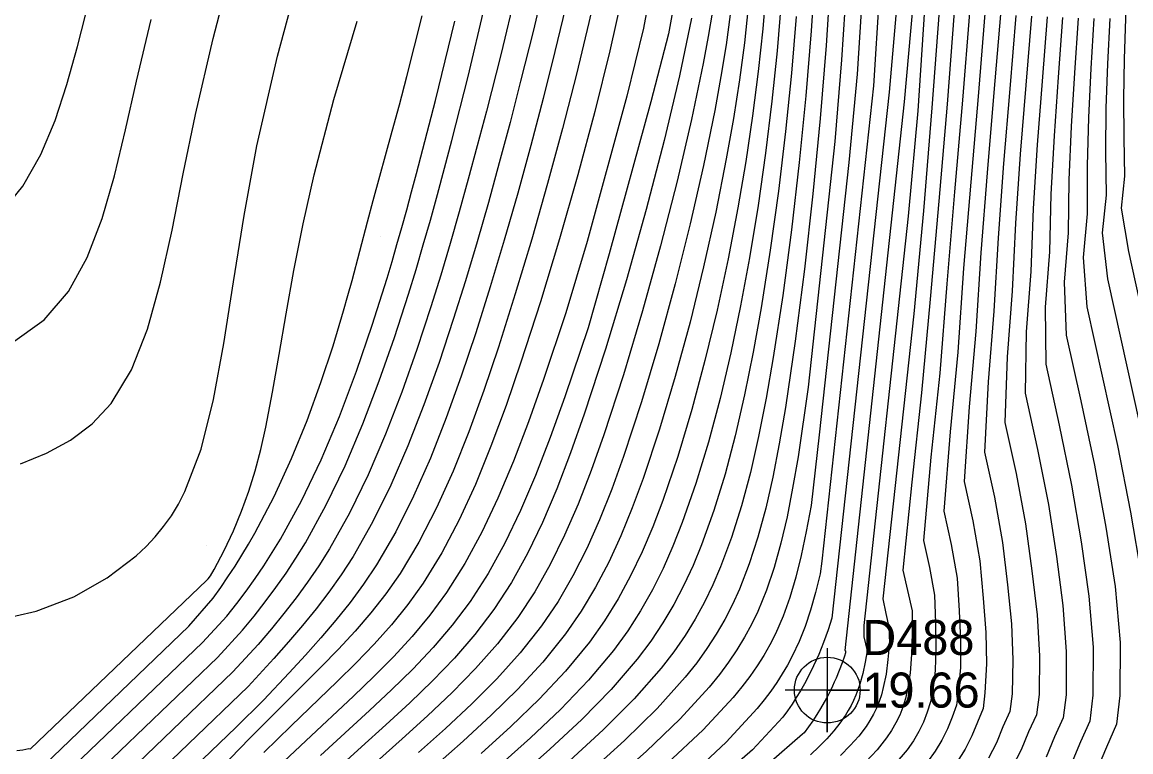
# Model space of a CAD drawing. Extents: x 2356077 to 2359823, y 225951 to 227822.
# Drawn here: x 2356768.9 to 2356848, y 226939 to 226991.1 of the extents above; entities that cross this region are included whole.
import ezdxf

# ---------------------------------------------------------------- set-up
doc = ezdxf.new("R2010")
doc.units = 0
for name, color, linetype in [('DTM Contours Major', 7, 'Continuous'), ('DTM Contours Minor', 7, 'Continuous'), ('Exist DTM Regular Point CELL', 7, 'Continuous'), ('Exist DTM Regular Point Cogo Elevation', 7, 'Continuous'), ('Exist DTM Regular Point Cogo Number', 7, 'Continuous'), ('PH Exist DTM Point', 7, 'Continuous')]:
    doc.layers.add(name, color=color, linetype=linetype)

msp = doc.modelspace()

# ---------------------------------------------------------------- linework, layer by layer
at = {"layer": 'DTM Contours Major'}
for points in [[(2356809.909, 226993.635), (2356809.32, 226991.039), (2356808.425, 226987.333), (2356807.438, 226983.481), (2356806.373, 226979.545), (2356805.246, 226975.589), (2356804.071, 226971.678), (2356802.862, 226967.875), (2356801.819, 226964.784), (2356800.747, 226961.832), (2356799.629, 226959.037), (2356798.452, 226956.414), (2356797.198, 226953.98), (2356795.853, 226951.751), (2356794.838, 226950.302), (2356793.769, 226948.938), (2356792.646, 226947.631), (2356791.467, 226946.356), (2356790.233, 226945.087), (2356788.944, 226943.796), (2356787.073, 226941.938), (2356785.109, 226939.968), (2356783.064, 226937.861)], [(2356830.007, 226992.945), (2356829.607, 226986.516), (2356825.924, 226952.62), (2356825.802, 226951.72), (2356825.476, 226950.376), (2356825.123, 226949.133), (2356824.736, 226947.975), (2356824.306, 226946.888), (2356823.823, 226945.856), (2356823.482, 226945.215), (2356823.113, 226944.587), (2356822.715, 226943.968), (2356822.286, 226943.354), (2356821.823, 226942.741), (2356821.326, 226942.124), (2356819.099, 226939.709), (2356816.463, 226937.248)], [(2356818.127, 226991.834), (2356817.829, 226990.035), (2356817.471, 226988.108), (2356816.631, 226984.102), (2356815.603, 226979.718), (2356814.427, 226975.115), (2356813.139, 226970.458), (2356811.778, 226965.907), (2356810.381, 226961.623), (2356809.476, 226959.077), (2356808.552, 226956.696), (2356807.587, 226954.47), (2356806.562, 226952.386), (2356805.454, 226950.433), (2356804.262, 226948.596), (2356802.802, 226946.729), (2356801.235, 226944.957), (2356799.566, 226943.257), (2356797.817, 226941.602), (2356796.008, 226939.965), (2356794.163, 226938.318)], [(2356768.047, 226968.083), (2356770.473, 226969.83), (2356772.197, 226971.856), (2356773.546, 226974.28), (2356774.614, 226977.045), (2356775.492, 226980.096), (2356776.274, 226983.378), (2356777.05, 226986.834), (2356778.1, 226991.252)], [(2356770.848, 226936.354), (2356781.758, 226946.817), (2356783.504, 226948.699), (2356784.2, 226949.595), (2356784.87, 226950.49), (2356785.515, 226951.389), (2356786.137, 226952.299), (2356786.739, 226953.228), (2356787.323, 226954.181), (2356788.833, 226956.921), (2356790.233, 226959.856), (2356791.534, 226962.947), (2356792.744, 226966.16), (2356793.87, 226969.457), (2356794.921, 226972.802), (2356795.278, 226973.996), (2356795.63, 226975.2), (2356795.978, 226976.421), (2356796.326, 226977.667), (2356796.676, 226978.947), (2356797.031, 226980.268), (2356798.376, 226985.47), (2356799.747, 226991.115)], [(2356824.099, 226991.457), (2356823.764, 226987.423), (2356823.341, 226983.244), (2356822.836, 226979.006), (2356822.257, 226974.795), (2356821.611, 226970.695), (2356821.042, 226967.515), (2356820.426, 226964.47), (2356819.757, 226961.569), (2356819.026, 226958.818), (2356818.228, 226956.225), (2356817.354, 226953.796), (2356816.747, 226952.322), (2356816.093, 226950.908), (2356815.381, 226949.543), (2356814.598, 226948.217), (2356813.732, 226946.917), (2356812.771, 226945.633), (2356810.912, 226943.473), (2356808.812, 226941.33), (2356806.539, 226939.206), (2356804.161, 226937.103)], [(2356835.373, 226991.796), (2356834.857, 226985.213), (2356834.264, 226978.279), (2356833.659, 226971.29), (2356833.044, 226964.612), (2356832.353, 226958.246), (2356831.718, 226951.989), (2356832.361, 226949.074), (2356832.371, 226947.454), (2356832.327, 226945.977), (2356832.229, 226944.652), (2356832.05, 226943.46), (2356831.9, 226942.824), (2356831.712, 226942.221), (2356831.485, 226941.646), (2356831.217, 226941.092), (2356830.906, 226940.555), (2356830.55, 226940.029), (2356829.864, 226939.174), (2356829.058, 226938.318)], [(2356840.879, 226991.473), (2356840.084, 226981.638), (2356839.741, 226976.721), (2356839.512, 226971.868), (2356839.143, 226967.194), (2356838.98, 226962.506), (2356839.782, 226958.875), (2356840.449, 226955.29), (2356840.913, 226951.936), (2356841.279, 226948.792), (2356841.445, 226945.877), (2356841.42, 226943.121), (2356841.233, 226941.667), (2356840.67, 226940.446), (2356840.15, 226939.164), (2356839.498, 226937.933)], [(2356846.463, 226991.315), (2356846.306, 226988.069), (2356846.19, 226984.918), (2356846.149, 226981.814), (2356846.211, 226978.707), (2356845.921, 226976.037), (2356846.301, 226972.756), (2356848.604, 226962.327)]]:
    msp.add_lwpolyline(points, dxfattribs=at)
at = {"layer": 'DTM Contours Minor'}
for points in [[(2356848.021, 227001.185), (2356847.797, 226996.149), (2356847.597, 226991.324), (2356847.499, 226988.406), (2356847.447, 226985.582), (2356847.465, 226982.801), (2356847.523, 226980.071), (2356847.277, 226977.801), (2356847.79, 226974.694), (2356851.417, 226958.266)], [(2356766.972, 226948.397), (2356769.899, 226949.052), (2356772.578, 226950.084), (2356774.97, 226951.424), (2356777.036, 226953.002), (2356777.739, 226953.662), (2356778.39, 226954.354), (2356778.99, 226955.084), (2356779.543, 226955.86), (2356780.05, 226956.689), (2356780.513, 226957.577), (2356781.662, 226960.597), (2356782.551, 226964.14), (2356783.286, 226968.141), (2356783.975, 226972.534), (2356784.724, 226977.255), (2356785.643, 226982.239), (2356787.108, 226988.625), (2356788.857, 226995.076)], [(2356768.791, 226959.569), (2356770.636, 226960.323), (2356772.353, 226961.255), (2356773.906, 226962.419), (2356775.261, 226963.869), (2356776.708, 226966.26), (2356777.85, 226969.163), (2356778.78, 226972.506), (2356779.595, 226976.218), (2356780.389, 226980.229), (2356781.257, 226984.466), (2356782.525, 226989.888), (2356783.962, 226995.383)], [(2356814.063, 226995.245), (2356813.202, 226990.635), (2356812.02, 226985.774), (2356809.185, 226975.404), (2356807.672, 226970.338), (2356806.082, 226965.579), (2356805.01, 226962.562), (2356803.935, 226959.744), (2356802.835, 226957.122), (2356801.69, 226954.69), (2356800.475, 226952.444), (2356799.17, 226950.38), (2356797.981, 226948.767), (2356796.717, 226947.251), (2356795.383, 226945.804), (2356793.982, 226944.395), (2356792.522, 226942.996), (2356789.131, 226939.821), (2356787.193, 226937.976)], [(2356815.826, 226994.835), (2356814.989, 226990.209), (2356813.731, 226985.368), (2356810.77, 226974.533), (2356809.259, 226969.249), (2356807.6, 226964.343), (2356806.55, 226961.437), (2356805.501, 226958.733), (2356804.43, 226956.223), (2356803.312, 226953.896), (2356802.125, 226951.742), (2356800.846, 226949.752), (2356799.571, 226948.054), (2356798.208, 226946.456), (2356796.766, 226944.93), (2356795.253, 226943.445), (2356793.68, 226941.972), (2356790.185, 226938.759)], [(2356825.446, 226994.757), (2356825.167, 226990.424), (2356824.785, 226985.807), (2356824.313, 226981.038), (2356823.761, 226976.247), (2356823.141, 226971.567), (2356822.464, 226967.131), (2356821.961, 226964.233), (2356821.424, 226961.51), (2356820.842, 226958.955), (2356820.204, 226956.559), (2356819.499, 226954.314), (2356818.714, 226952.212), (2356818.161, 226950.93), (2356817.561, 226949.694), (2356816.903, 226948.494), (2356816.178, 226947.318), (2356815.374, 226946.157), (2356814.482, 226945), (2356812.546, 226942.803), (2356810.339, 226940.596), (2356807.942, 226938.391)], [(2356826.558, 226994.268), (2356826.241, 226989.392), (2356825.814, 226984.173), (2356825.279, 226978.809), (2356824.696, 226973.449), (2356824.04, 226968.315), (2356823.336, 226963.581), (2356822.896, 226960.998), (2356822.431, 226958.609), (2356821.928, 226956.394), (2356821.373, 226954.337), (2356820.752, 226952.42), (2356820.051, 226950.623), (2356819.552, 226949.523), (2356819.005, 226948.457), (2356818.404, 226947.415), (2356817.74, 226946.387), (2356817.006, 226945.365), (2356816.193, 226944.34), (2356814.183, 226942.112), (2356811.869, 226939.845), (2356809.346, 226937.562)], [(2356806.226, 226994.187), (2356805.358, 226990.488), (2356804.452, 226986.847), (2356803.695, 226983.909), (2356802.93, 226981.025), (2356802.15, 226978.187), (2356801.348, 226975.385), (2356800.516, 226972.608), (2356799.65, 226969.847), (2356798.634, 226966.787), (2356797.559, 226963.773), (2356796.415, 226960.844), (2356795.197, 226958.038), (2356793.896, 226955.396), (2356792.504, 226952.955), (2356791.66, 226951.653), (2356790.78, 226950.411), (2356789.862, 226949.212), (2356788.904, 226948.034), (2356787.902, 226946.861), (2356786.854, 226945.672), (2356785.025, 226943.695), (2356776.5, 226935.519)], [(2356821.96, 226993.528), (2356821.717, 226990.584), (2356821.393, 226987.524), (2356820.988, 226984.364), (2356820.504, 226981.118), (2356819.94, 226977.803), (2356819.243, 226974.17), (2356818.461, 226970.527), (2356817.598, 226966.93), (2356816.66, 226963.432), (2356815.655, 226960.088), (2356814.587, 226956.952), (2356813.867, 226955.065), (2356813.107, 226953.276), (2356812.292, 226951.571), (2356811.406, 226949.939), (2356810.433, 226948.368), (2356809.356, 226946.847), (2356807.659, 226944.782), (2356805.775, 226942.778), (2356803.75, 226940.822), (2356801.629, 226938.901)], [(2356827.681, 226993.798), (2356827.33, 226988.365), (2356826.849, 226982.554), (2356824.945, 226965.034), (2356824.233, 226960.062), (2356823.849, 226957.825), (2356823.447, 226955.777), (2356823.01, 226953.896), (2356822.526, 226952.159), (2356821.98, 226950.545), (2356821.357, 226949.031), (2356820.91, 226948.099), (2356820.419, 226947.192), (2356819.878, 226946.301), (2356819.282, 226945.418), (2356818.625, 226944.535), (2356817.901, 226943.644), (2356815.821, 226941.386), (2356813.402, 226939.062), (2356810.751, 226936.703)], [(2356767.305, 226977.352), (2356768.945, 226979.367), (2356770.232, 226981.605), (2356771.253, 226984.033), (2356772.095, 226986.618), (2356772.844, 226989.327), (2356773.737, 226992.787)], [(2356804.094, 226993.113), (2356803.057, 226988.816), (2356802.012, 226984.714), (2356801.361, 226982.234), (2356800.719, 226979.848), (2356800.076, 226977.531), (2356799.423, 226975.259), (2356798.75, 226973.01), (2356798.047, 226970.758), (2356797.045, 226967.712), (2356795.968, 226964.668), (2356794.811, 226961.675), (2356793.57, 226958.781), (2356792.239, 226956.036), (2356790.814, 226953.489), (2356790.051, 226952.28), (2356789.259, 226951.121), (2356788.435, 226949.996), (2356787.575, 226948.891), (2356786.678, 226947.791), (2356785.739, 226946.682), (2356783.923, 226944.723), (2356775.317, 226936.47)], [(2356811.721, 226993.075), (2356810.812, 226989.014), (2356809.737, 226984.671), (2356808.53, 226980.163), (2356807.227, 226975.605), (2356805.861, 226971.113), (2356804.467, 226966.802), (2356803.409, 226963.724), (2356802.335, 226960.821), (2356801.226, 226958.098), (2356800.064, 226955.561), (2356798.829, 226953.214), (2356797.502, 226951.063), (2356796.399, 226949.528), (2356795.231, 226948.086), (2356794.001, 226946.708), (2356792.712, 226945.366), (2356791.364, 226944.032), (2356788.09, 226940.878), (2356786.144, 226938.978)], [(2356831.307, 226992.649), (2356830.721, 226986.06), (2356826.646, 226948.559), (2356826.374, 226947.721), (2356826.052, 226946.83), (2356825.709, 226945.977), (2356825.343, 226945.157), (2356824.951, 226944.366), (2356824.684, 226943.87), (2356824.404, 226943.383), (2356824.111, 226942.903), (2356823.804, 226942.428), (2356823.484, 226941.959), (2356823.149, 226941.492), (2356820.979, 226939.176), (2356808.524, 226928.333)], [(2356828.823, 226993.35), (2356828.453, 226987.355), (2356827.85, 226981.057), (2356825.738, 226961.621), (2356825.159, 226956.594), (2356824.822, 226954.731), (2356824.467, 226953.03), (2356824.081, 226951.472), (2356823.654, 226950.034), (2356823.171, 226948.696), (2356822.62, 226947.437), (2356822.224, 226946.659), (2356821.791, 226945.898), (2356821.317, 226945.148), (2356820.798, 226944.403), (2356820.23, 226943.657), (2356819.609, 226942.904), (2356817.46, 226940.6), (2356814.935, 226938.214)], [(2356774.148, 226937.433), (2356782.828, 226945.758), (2356784.619, 226947.695), (2356785.444, 226948.711), (2356786.233, 226949.723), (2356786.99, 226950.74), (2356787.719, 226951.773), (2356788.421, 226952.832), (2356789.099, 226953.929), (2356790.564, 226956.58), (2356791.929, 226959.423), (2356793.196, 226962.405), (2356794.369, 226965.474), (2356795.454, 226968.578), (2356796.452, 226971.665), (2356796.99, 226973.418), (2356797.509, 226975.17), (2356798.015, 226976.943), (2356798.518, 226978.76), (2356799.023, 226980.642), (2356799.54, 226982.612), (2356800.701, 226987.188), (2356801.883, 226992.109)], [(2356807.648, 226992.098), (2356806.891, 226988.96), (2356806.051, 226985.618), (2356805.169, 226982.248), (2356804.247, 226978.87), (2356803.286, 226975.506), (2356802.287, 226972.174), (2356801.252, 226968.895), (2356800.221, 226965.815), (2356799.146, 226962.829), (2356798.016, 226959.965), (2356796.819, 226957.249), (2356795.544, 226954.708), (2356794.18, 226952.37), (2356793.254, 226950.986), (2356792.285, 226949.672), (2356791.271, 226948.407), (2356790.21, 226947.167), (2356789.102, 226945.929), (2356787.943, 226944.67), (2356786.108, 226942.701), (2356784.138, 226940.76), (2356777.676, 226934.562)], [(2356820.68, 226992.129), (2356820.404, 226989.589), (2356820.053, 226986.943), (2356819.624, 226984.186), (2356819.116, 226981.31), (2356818.362, 226977.513), (2356817.495, 226973.601), (2356816.529, 226969.66), (2356815.479, 226965.776), (2356814.361, 226962.035), (2356813.189, 226958.523), (2356812.409, 226956.419), (2356811.596, 226954.434), (2356810.731, 226952.555), (2356809.797, 226950.77), (2356808.776, 226949.068), (2356807.651, 226947.437), (2356806.037, 226945.43), (2356804.26, 226943.501), (2356802.355, 226941.63), (2356800.361, 226939.799), (2356798.314, 226937.988)], [(2356823.031, 226992.491), (2356822.743, 226989.015), (2356822.37, 226985.408), (2356821.914, 226981.715), (2356821.38, 226977.983), (2356820.77, 226974.258), (2356820.136, 226970.831), (2356819.438, 226967.479), (2356818.674, 226964.23), (2356817.844, 226961.111), (2356816.945, 226958.15), (2356815.976, 226955.376), (2356815.314, 226953.7), (2356814.607, 226952.101), (2356813.843, 226950.568), (2356813.007, 226949.089), (2356812.085, 226947.652), (2356811.063, 226946.247), (2356809.284, 226944.131), (2356807.293, 226942.056), (2356805.144, 226940.015), (2356802.896, 226938.003)], [(2356832.41, 226992.266), (2356831.809, 226985.365), (2356827.559, 226946.255), (2356827.611, 226946.217), (2356827.614, 226946.096), (2356827.548, 226945.853), (2356827.377, 226945.37), (2356827.169, 226944.821), (2356826.95, 226944.291), (2356826.819, 226943.992), (2356826.684, 226943.698), (2356826.545, 226943.409), (2356826.402, 226943.124), (2356826.254, 226942.844), (2356826.102, 226942.568), (2356825.842, 226942.12), (2356825.568, 226941.68), (2356825.281, 226941.247), (2356824.979, 226940.817), (2356824.663, 226940.391), (2356824.551, 226940.282), (2356812.545, 226929.831)], [(2356833.245, 226991.968), (2356832.767, 226984.741), (2356832.086, 226977.208), (2356828.917, 226948.041), (2356828.933, 226947.237), (2356829.154, 226946.237), (2356829.029, 226945.421), (2356828.849, 226944.606), (2356828.641, 226943.859), (2356828.504, 226943.453), (2356828.355, 226943.064), (2356828.192, 226942.69), (2356828.014, 226942.328), (2356827.819, 226941.976), (2356827.607, 226941.631), (2356827.219, 226941.073), (2356826.778, 226940.52), (2356826.284, 226939.963), (2356825.735, 226939.396), (2356825.129, 226938.81)], [(2356834.291, 226991.868), (2356833.777, 226984.952), (2356833.169, 226977.602), (2356832.494, 226970.258), (2356830.287, 226949.94), (2356830.486, 226948.884), (2356830.702, 226947.905), (2356830.75, 226946.796), (2356830.645, 226945.619), (2356830.506, 226944.561), (2356830.315, 226943.608), (2356830.176, 226943.097), (2356830.012, 226942.611), (2356829.823, 226942.148), (2356829.607, 226941.702), (2356829.362, 226941.269), (2356829.086, 226940.844), (2356828.563, 226940.155), (2356827.953, 226939.467), (2356827.255, 226938.767)], [(2356768.516, 226939.113), (2356768.953, 226939.175), (2356769.388, 226939.26), (2356769.503, 226939.233), (2356782.037, 226951.254), (2356782.169, 226951.366), (2356782.34, 226951.581), (2356782.597, 226952.033), (2356782.843, 226952.482), (2356783.08, 226952.928), (2356783.307, 226953.372), (2356783.971, 226954.775), (2356784.552, 226956.178), (2356785.063, 226957.601), (2356785.514, 226959.063), (2356785.916, 226960.583), (2356786.28, 226962.178), (2356786.767, 226964.666), (2356787.237, 226967.357), (2356787.729, 226970.252), (2356788.281, 226973.353), (2356788.934, 226976.661), (2356789.726, 226980.178), (2356791.14, 226985.539), (2356792.799, 226991.13)], [(2356769.888, 226937.518), (2356780.8, 226947.983), (2356782.518, 226949.973), (2356783.059, 226950.738), (2356783.581, 226951.503), (2356784.087, 226952.272), (2356784.575, 226953.048), (2356785.048, 226953.832), (2356785.507, 226954.627), (2356786.876, 226957.236), (2356788.113, 226959.93), (2356789.223, 226962.654), (2356790.209, 226965.353), (2356791.075, 226967.973), (2356791.826, 226970.46), (2356792.139, 226971.566), (2356792.434, 226972.641), (2356792.99, 226974.732), (2356793.536, 226976.808), (2356793.945, 226978.325), (2356795.299, 226983.287), (2356795.801, 226985.154), (2356796.33, 226987.166), (2356797.429, 226991.493)], [(2356816.642, 226991.346), (2356815.784, 226987.23), (2356814.687, 226982.616), (2356813.406, 226977.699), (2356811.992, 226972.677), (2356810.499, 226967.745), (2356808.98, 226963.1), (2356808.008, 226960.345), (2356807.024, 226957.779), (2356806.008, 226955.39), (2356804.938, 226953.168), (2356803.791, 226951.101), (2356802.546, 226949.179), (2356801.187, 226947.386), (2356799.723, 226945.697), (2356798.168, 226944.083), (2356796.539, 226942.513), (2356794.848, 226940.96), (2356793.112, 226939.392), (2356791.248, 226937.696)], [(2356819.398, 226991.593), (2356819.102, 226989.439), (2356818.734, 226987.167), (2356818.294, 226984.756), (2356817.491, 226980.838), (2356816.542, 226976.679), (2356815.471, 226972.402), (2356814.304, 226968.128), (2356813.068, 226963.982), (2356811.786, 226960.084), (2356810.945, 226957.759), (2356810.077, 226955.575), (2356809.162, 226953.522), (2356808.182, 226951.586), (2356807.117, 226949.756), (2356805.947, 226948.02), (2356804.418, 226946.078), (2356802.747, 226944.226), (2356800.961, 226942.441), (2356799.09, 226940.699), (2356797.163, 226938.976)], [(2356836.466, 226991.728), (2356835.962, 226985.483), (2356835.396, 226978.964), (2356834.837, 226972.403), (2356834.352, 226966.036), (2356833.711, 226960.039), (2356833.171, 226954.087), (2356833.597, 226952.161), (2356833.971, 226950.208), (2356834.035, 226948.226), (2356834.06, 226946.437), (2356834.006, 226944.823), (2356833.837, 226943.369), (2356833.671, 226942.592), (2356833.452, 226941.855), (2356833.178, 226941.153), (2356832.847, 226940.478), (2356832.457, 226939.823), (2356832.008, 226939.181), (2356831.138, 226938.136)], [(2356837.565, 226991.661), (2356837.08, 226985.754), (2356836.549, 226979.643), (2356836.039, 226973.506), (2356835.62, 226967.521), (2356835.07, 226961.834), (2356834.624, 226956.19), (2356835.148, 226953.815), (2356835.575, 226951.399), (2356835.728, 226949.078), (2356835.829, 226946.964), (2356835.825, 226945.045), (2356835.664, 226943.309), (2356835.536, 226942.354), (2356835.224, 226941.501), (2356834.895, 226940.662), (2356834.493, 226939.855), (2356834.016, 226939.072), (2356833.462, 226938.304)], [(2356838.667, 226991.596), (2356838.207, 226986.025), (2356837.716, 226980.315), (2356837.259, 226974.594), (2356836.904, 226968.989), (2356836.428, 226963.626), (2356836.075, 226958.298), (2356836.696, 226955.486), (2356837.192, 226952.652), (2356837.443, 226949.989), (2356837.626, 226947.541), (2356837.676, 226945.302), (2356837.559, 226943.242), (2356837.432, 226942.119), (2356837.021, 226941.15), (2356836.632, 226940.167), (2356836.152, 226939.222), (2356835.579, 226938.305)], [(2356839.771, 226991.532), (2356839.342, 226986.296), (2356838.895, 226980.979), (2356838.494, 226975.665), (2356838.202, 226970.439), (2356837.786, 226965.413), (2356837.527, 226960.404), (2356838.241, 226957.173), (2356838.818, 226953.952), (2356839.172, 226950.945), (2356839.445, 226948.153), (2356839.551, 226945.581), (2356839.492, 226943.173), (2356839.331, 226941.891), (2356838.838, 226940.799), (2356838.385, 226939.668), (2356837.821, 226938.581)], [(2356841.988, 226991.42), (2356841.632, 226986.851), (2356841.285, 226982.294), (2356841, 226977.763), (2356840.832, 226973.277), (2356840.499, 226968.969), (2356840.435, 226964.598), (2356841.32, 226960.59), (2356842.085, 226956.657), (2356842.662, 226952.955), (2356843.125, 226949.451), (2356843.354, 226946.184), (2356843.345, 226943.085), (2356843.137, 226941.445), (2356842.515, 226940.09), (2356841.924, 226938.656)], [(2356843.101, 226991.376), (2356842.789, 226987.139), (2356842.495, 226982.948), (2356842.27, 226978.793), (2356842.163, 226974.665), (2356841.855, 226970.74), (2356841.893, 226966.676), (2356842.856, 226962.315), (2356843.724, 226958.048), (2356844.419, 226953.996), (2356844.982, 226950.125), (2356845.276, 226946.497), (2356845.267, 226943.062), (2356845.042, 226941.224), (2356844.37, 226939.729), (2356843.707, 226938.143)], [(2356844.216, 226991.342), (2356843.952, 226987.437), (2356843.716, 226983.602), (2356843.551, 226979.81), (2356843.503, 226976.033), (2356843.211, 226972.508), (2356843.355, 226968.734), (2356844.39, 226964.046), (2356845.366, 226959.456), (2356846.181, 226955.051), (2356846.847, 226950.809), (2356847.207, 226946.812), (2356847.186, 226943.051), (2356846.947, 226941.006), (2356846.233, 226939.364), (2356845.496, 226937.626)], [(2356845.337, 226991.321), (2356845.124, 226987.746), (2356844.947, 226984.259), (2356844.844, 226980.817), (2356844.852, 226977.381), (2356844.566, 226974.273), (2356844.824, 226970.764), (2356847.008, 226960.875), (2356847.947, 226956.115), (2356848.719, 226951.496)]]:
    msp.add_lwpolyline(points, dxfattribs=at)
at = {"layer": 'Exist DTM Regular Point CELL'}
msp.add_lwpolyline([(2356826.318, 226946.429), (2356826.318, 226940.429), (2356826.318, 226943.429), (2356829.318, 226943.429), (2356823.318, 226943.429)], dxfattribs=at)
msp.add_circle((2356826.318, 226943.429), 2.344, dxfattribs=at)
at = {"layer": 'PH Exist DTM Point'}
for p, q in [((2356794.439, 226975.766), (2356794.439, 226975.766)), ((2356782.066, 226953.755), (2356782.066, 226953.755))]:
    msp.add_line(p, q, dxfattribs=at)

# ---------------------------------------------------------------- texts
at = {"layer": 'Exist DTM Regular Point Cogo Elevation'}
msp.add_text('19.66', height=2.5, dxfattribs=at).set_placement((2356828.818, 226942.179))
at = {"layer": 'Exist DTM Regular Point Cogo Number'}
msp.add_text('D488', height=2.5, dxfattribs=at).set_placement((2356828.818, 226945.929))

doc.saveas('drawing.dxf')
